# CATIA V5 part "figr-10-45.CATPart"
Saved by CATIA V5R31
Part number: Part1
Bounding box of the stored display mesh (mm): x -20 to 20, y -41.679 to 32.292, z -5.268 to 19.6
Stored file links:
  D:\PROJECTS\Project 2021\US EDITION\CATIA V5 6R 2021\Resources\Part Files\c10_catia_v5_6r2021_prt\c10_catia_v5_6r2021_prt\figr-10-45.CATPart
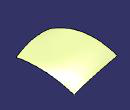
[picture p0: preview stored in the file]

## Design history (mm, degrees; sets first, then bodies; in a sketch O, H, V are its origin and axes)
Set1
  Plane1: type Offset, RefPlane yz-plane, Offset 20, reversed
  Plane2: type Offset, RefPlane yz-plane, Offset 20
  Sketch1 on Plane1, origin (-20, 0, 0), H (0, 1, 0), V (0, 0, 1)
    spline S1 through (-41.3356, 3.6998) (10.9718, 19.5196) (47.9697, 8.2926)
  Sketch2 on yz-plane, origin (0, 0, 0), H (0, 1, 0), V (0, 0, 1)
    spline S1 through (-41.087, 1.981) (-29.2011, 1.8342) (-9.0978, 3.8886) (28.3207, 0)
    point P1 (28.3207, 0)
    coincidence: P1 H
  Sketch3 on Plane2, origin (20, 0, 0), H (0, 1, 0), V (0, 0, 1)
    spline S1 through (-41.7094, -2.237) (-14.4323, 0.9381) (25.2566, -5.2678)
  Plane3: type Offset, RefPlane yz-plane, Offset 10
  Sketch4 on Plane3, origin (10, 0, 0), H (0, 1, 0), V (0, 0, 1)
    spline S1 through (-45.2274, 0) (26.2784, 6.3461) (36.8255, 3.6647)
    point P1 (-45.2274, 0)
    coincidence: P1 H
  Sweep1: type Conic, Guide ({sweepconicextendedguide Guide Sketch1, Reference Sketch2, Angle 15}; {sweepconicextendedguide Guide Sketch3, Reference Sketch4, Angle 0}), Parameter 0.5
Body1 (main body)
